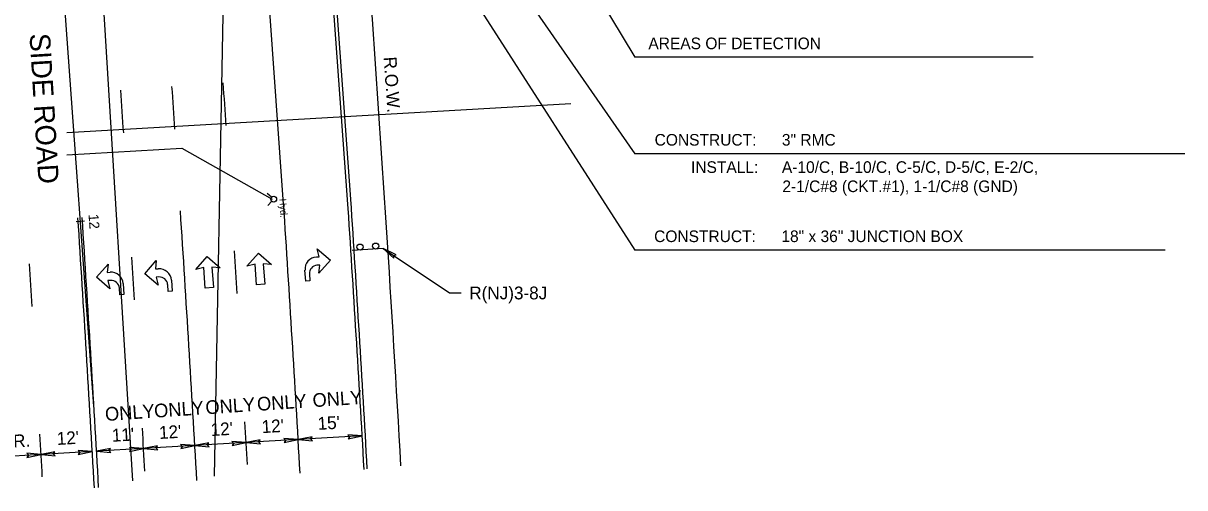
# Model space of a CAD drawing. Extents: x 488740 to 507913, y 466518 to 497949.
# Drawn here: x 503498.7 to 503770.5, y 495808.3 to 495917 of the extents above; entities that cross this region are included whole.
import ezdxf

# ---------------------------------------------------------------- set-up
doc = ezdxf.new("R2010")
doc.units = 0
for name, color, linetype in [('1', 7, 'Continuous'), ('10', 7, 'Continuous'), ('23', 7, 'Continuous'), ('36', 7, 'Continuous'), ('38', 7, 'Continuous'), ('42', 7, 'Continuous')]:
    doc.layers.add(name, color=color, linetype=linetype)

msp = doc.modelspace()

# ---------------------------------------------------------------- linework, layer by layer
at = {"layer": '1'}
for p, q in [((503515.23, 495827.41), (503497.67, 496070.42)), ((503574.61, 495875.73), (503568.16, 495964.96)), ((503575.36, 495875.79), (503568.91, 495965.02)), ((503513.09, 495870.69), (503511.1, 495870.54))]:
    msp.add_line(p, q, dxfattribs=at)
for centre, radius, start, end in [((496341.87, 495401.78), 7256.91, 3.252403, 4.133489), ((496341.87, 495401.78), 7248.26, 3.249458, 3.748381), ((496342.61, 495401.93), 7248.26, 3.249458, 3.748381)]:
    msp.add_arc(centre, radius, start, end, dxfattribs=at)
at = {"layer": '10'}
for p, q in [((503593.88, 495988.3), (503641.84, 495909.01)), ((503576.6, 495980.13), (503641.84, 495886.46)), ((503572.7, 495971.48), (503641.84, 495863.9)), ((503735.02, 495909.01), (503641.84, 495909.01)), ((503770.46, 495886.46), (503641.84, 495886.46)), ((503765.85, 495863.9), (503641.84, 495863.9))]:
    msp.add_line(p, q, dxfattribs=at)
at = {"layer": '23'}
for p, q in [((503524.39, 495809.94), (503494.31, 496296.44)), ((503546.14, 495959.54), (503543.42, 495811.02)), ((503508.94, 495891.45), (503626.81, 495898.16)), ((503508.94, 495886.21), (503535.84, 495887.75)), ((503535.84, 495887.75), (503556.97, 495875.85)), ((503556.81, 495876.28), (503555.81, 495877.18)), ((503556.87, 495875.33), (503555.96, 495874.32))]:
    msp.add_line(p, q, dxfattribs=at)
msp.add_circle((503557.32, 495875.83), 0.675, dxfattribs=at)
at = {"layer": '36'}
for p, q in [((503559.65, 495874.65), (503550.66, 495999.1)), ((503567.95, 495862.35), (503567.49, 495864.25)), ((503567.49, 495864.25), (503570.58, 495861.58)), ((503527.2, 495858.37), (503529.86, 495861.46)), ((503529.86, 495861.46), (503529.68, 495859.51)), ((503539.08, 495859.36), (503541.75, 495862.44)), ((503541.75, 495862.44), (503544.83, 495859.77)), ((503551.07, 495860.15), (503553.74, 495863.23)), ((503553.74, 495863.23), (503556.83, 495860.56)), ((503567.31, 495862.31), (503567.95, 495862.35)), ((503570.58, 495861.58), (503567.91, 495858.49)), ((503515.9, 495857.55), (503518.57, 495860.64)), ((503518.57, 495860.64), (503518.39, 495858.7)), ((503518.39, 495858.7), (503519.03, 495858.74)), ((503530.28, 495855.7), (503527.2, 495858.37)), ((503529.68, 495859.51), (503530.32, 495859.56)), ((503540.97, 495859.82), (503539.08, 495859.36)), ((503541.32, 495855.02), (503540.97, 495859.82)), ((503544.83, 495859.77), (503542.89, 495859.95)), ((503542.89, 495859.95), (503543.24, 495855.16)), ((503552.97, 495860.6), (503551.07, 495860.15)), ((503553.32, 495855.81), (503552.97, 495860.6)), ((503556.83, 495860.56), (503554.89, 495860.74)), ((503554.89, 495860.74), (503555.23, 495855.95)), ((503564.83, 495856.66), (503564.64, 495859.22)), ((503565.67, 495858.33), (503565.78, 495856.73)), ((503568.09, 495860.43), (503567.45, 495860.39)), ((503567.91, 495858.49), (503568.09, 495860.43)), ((503518.99, 495854.89), (503515.9, 495857.55)), ((503519.17, 495856.83), (503518.53, 495856.78)), ((503518.53, 495856.78), (503518.99, 495854.89)), ((503522.11, 495856.08), (503522.3, 495853.52)), ((503530.46, 495857.64), (503529.82, 495857.6)), ((503529.82, 495857.6), (503530.28, 495855.7)), ((503532.63, 495854.26), (503532.52, 495855.86)), ((503533.41, 495856.89), (503533.59, 495854.33)), ((503555.23, 495855.95), (503553.32, 495855.81)), ((503565.78, 495856.73), (503564.83, 495856.66)), ((503521.34, 495853.45), (503521.22, 495855.05)), ((503522.3, 495853.52), (503521.34, 495853.45)), ((503533.59, 495854.33), (503532.63, 495854.26)), ((503543.24, 495855.16), (503541.32, 495855.02))]:
    msp.add_line(p, q, dxfattribs=at)
for centre, radius, start, end in [((496341.87, 495401.78), 7209.05, 3.900689, 3.980294), ((496341.87, 495401.78), 7221.07, 3.900822, 3.980294), ((496341.87, 495401.78), 7197.03, 3.900558, 3.980294), ((496341.87, 495401.78), 7233.26, 3.249458, 3.748381), ((496341.87, 495401.78), 7209.05, 3.246589, 3.748344), ((496341.87, 495401.78), 7185.02, 3.243828, 3.748344), ((496341.87, 495401.78), 7186.02, 3.243828, 3.748344), ((496341.87, 495401.78), 7221.07, 3.588819, 3.668292), ((496341.87, 495401.78), 7197.03, 3.588553, 3.668292), ((503567.52, 495859.43), 2.88, 94.1344, 184.1344), ((496341.87, 495401.78), 7173, 3.588553, 3.668292), ((503519.24, 495855.87), 2.88, 4.1344, 94.1344), ((503530.53, 495856.68), 2.88, 4.1344, 94.1344), ((503567.59, 495858.47), 1.92, 94.1344, 184.1344), ((503519.31, 495854.91), 1.92, 4.1344, 94.1344), ((503530.6, 495855.72), 1.92, 4.1344, 94.1344), ((496341.87, 495401.78), 7221.07, 3.270925, 3.3504), ((496341.87, 495401.78), 7173, 3.2696, 3.349339), ((496341.87, 495401.78), 7197.03, 3.2696, 3.349339)]:
    msp.add_arc(centre, radius, start, end, dxfattribs=at)
at = {"layer": '38'}
for p, q in [((503578.02, 495820.46), (503563.05, 495819.6)), ((503526.89, 495817.5), (503515.89, 495816.87)), ((503538.89, 495818.2), (503526.89, 495817.5)), ((503550.88, 495818.89), (503538.89, 495818.2)), ((503563.05, 495819.6), (503550.88, 495818.89)), ((503502.89, 495816.12), (503489, 495815.31)), ((503514.89, 495816.81), (503502.89, 495816.12))]:
    msp.add_line(p, q, dxfattribs=at)
for points in [[(503563.05, 495819.6), (503566.38, 495819.32), (503565.99, 495819.77), (503566.32, 495820.26)], [(503578.02, 495820.46), (503574.69, 495820.74), (503575.07, 495820.29), (503574.75, 495819.8)], [(503515.89, 495816.87), (503519.22, 495816.59), (503518.83, 495817.04), (503519.16, 495817.53)], [(503526.89, 495817.5), (503523.56, 495817.78), (503523.94, 495817.33), (503523.61, 495816.84)], [(503526.89, 495817.5), (503530.22, 495817.22), (503529.83, 495817.67), (503530.16, 495818.17)], [(503538.89, 495818.2), (503535.56, 495818.48), (503535.94, 495818.03), (503535.61, 495817.54)], [(503538.89, 495818.2), (503542.21, 495817.92), (503541.83, 495818.37), (503542.16, 495818.86)], [(503550.88, 495818.89), (503547.56, 495819.17), (503547.94, 495818.72), (503547.61, 495818.23)], [(503550.88, 495818.89), (503554.21, 495818.61), (503553.83, 495819.06), (503554.16, 495819.56)], [(503563.05, 495819.6), (503559.72, 495819.88), (503560.1, 495819.43), (503559.77, 495818.93)], [(503502.89, 495816.12), (503499.56, 495816.4), (503499.94, 495815.94), (503499.61, 495815.45)], [(503502.89, 495816.12), (503506.22, 495815.83), (503505.84, 495816.29), (503506.16, 495816.78)], [(503514.89, 495816.81), (503511.56, 495817.09), (503511.94, 495816.64), (503511.61, 495816.15)]]:
    msp.add_lwpolyline(points, close=True, dxfattribs=at)
at = {"layer": '42'}
for p, q in [((503579.34, 495864.02), (503575.69, 495863.79)), ((503582.97, 495864.26), (503579.32, 495864.02)), ((503582.95, 495864.26), (503598.46, 495853.89)), ((503598.46, 495853.89), (503601.17, 495853.89))]:
    msp.add_line(p, q, dxfattribs=at)
msp.add_lwpolyline([(503582.95, 495864.26), (503585.44, 495862.03), (503585.41, 495862.62), (503585.97, 495862.81)], close=True, dxfattribs=at)
for centre in [(503577.53, 495864.62), (503581.16, 495864.85)]:
    msp.add_circle(centre, 0.721, dxfattribs=at)

# ---------------------------------------------------------------- texts
at = {"layer": '1'}
for s, height, rotation, p in [('SIDE ROAD', 4.796, 273.4605, (503500.19, 495914.48)), ('R.O.W.', 2.993, 273.9498, (503583.04, 495909.04)), ('12', 2.344, 274.1335, (503514, 495872.26))]:
    msp.add_text(s, height=height, rotation=rotation, dxfattribs=at).set_placement(p)
at = {"layer": '10'}
for s, height, p in [('AREAS OF DETECTION           ', 2.7163, (503644.98, 495910.9)), ('CONSTRUCT:', 2.716, (503646.44, 495888.35)), ('3" RMC                                  ', 2.7163, (503676.21, 495888.35)), ('INSTALL:', 2.716, (503654.95, 495881.97)), ('A-10/C, B-10/C, C-5/C, D-5/C, E-2/C,    ', 2.7163, (503676.21, 495881.97)), ('2-1/C#8 (CKT.#1), 1-1/C#8 (GND)         ', 2.7163, (503676.32, 495877.48)), ('CONSTRUCT:', 2.716, (503646.32, 495865.79)), ('18" x 36" JUNCTION BOX       ', 2.7163, (503676.09, 495865.79))]:
    msp.add_text(s, height=height, dxfattribs=at).set_placement(p)
at = {"layer": '23'}
msp.add_text('Hyd.', height=1.62, rotation=273.0981, dxfattribs=at).set_placement((503558.66, 495875.9))
at = {"layer": '36'}
for p in [(503566.52, 495827.18), (503529.46, 495824.71), (503541.46, 495825.51), (503553.53, 495826.31), (503517.97, 495823.95)]:
    msp.add_text('ONLY', height=3.193, rotation=3.8987, dxfattribs=at).set_placement(p)
at = {"layer": '38'}
for s, rotation, p in [("12'", 3.3111, (503530.59, 495819.74)), ("12'", 3.3116, (503542.67, 495820.43)), ("12'", 3.3112, (503554.59, 495821.11)), ("15'", 3.3116, (503567.68, 495821.87)), ('VAR.', 3.3115, (503491.13, 495817.43)), ("12'", 3.3116, (503506.66, 495818.34)), ("11'", 3.3113, (503519.54, 495819.09))]:
    msp.add_text(s, height=2.993, rotation=rotation, dxfattribs=at).set_placement(p)
at = {"layer": '42'}
msp.add_text('R(NJ)3-8J', height=2.993, dxfattribs=at).set_placement((503603.08, 495852.4))

doc.saveas('drawing.dxf')
